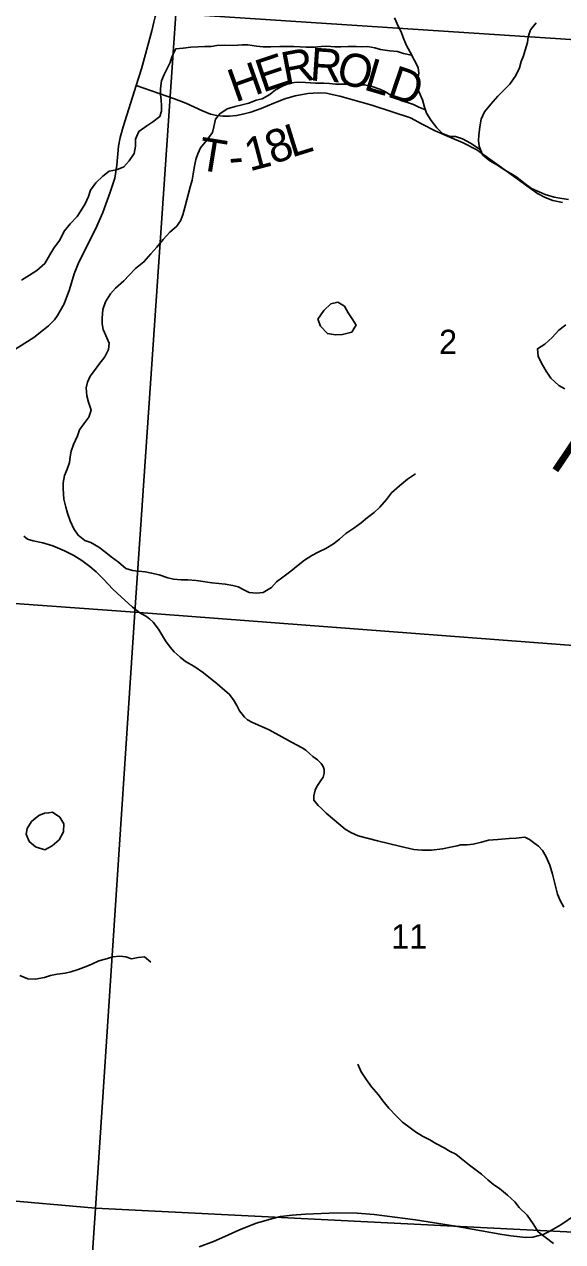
# Model space of a CAD drawing. Extents: x 0 to 34, y 0 to 22.
# Drawn here: x 24.527 to 25.453, y 16.992 to 19.088 of the extents above; entities that cross this region are included whole.
import ezdxf

# ---------------------------------------------------------------- set-up
doc = ezdxf.new("R2010")
doc.units = 0
for name, color, linetype in [('GM_X_Major_River', 7, 'Continuous'), ('GM_X_Major_River_Text', 7, 'Continuous'), ('GM_X_Minor_Lake', 7, 'Continuous'), ('GM_X_Minor_River', 7, 'Continuous'), ('GM_X_Section', 7, 'Continuous'), ('GM_X_Section_Text', 7, 'Continuous'), ('GM_X_State_Route', 7, 'Continuous'), ('GM_X_Township_Road', 7, 'Continuous'), ('GM_X_Township_Road_Text', 7, 'Continuous')]:
    doc.layers.add(name, color=color, linetype=linetype)

msp = doc.modelspace()

# ---------------------------------------------------------------- linework, layer by layer
at = {"layer": 'GM_X_Major_River'}
for points in [[(25.3133, 18.9253), (25.319, 18.9378), (25.3297, 18.9506), (25.342, 18.9645), (25.3515, 18.9747), (25.3626, 18.9856), (25.3726, 19.0004), (25.3791, 19.0136), (25.3822, 19.0242), (25.3861, 19.034), (25.3888, 19.0439), (25.3927, 19.0571), (25.3942, 19.067), (25.3981, 19.0787), (25.4077, 19.0908)], [(25.4633, 18.7865), (25.452, 18.7885), (25.4391, 18.7908), (25.4235, 18.7951), (25.4133, 18.8001), (25.3997, 18.8059), (25.3869, 18.8151), (25.3748, 18.8251), (25.3642, 18.8312), (25.3521, 18.8381), (25.3401, 18.8466), (25.328, 18.8535), (25.3155, 18.8638), (25.3095, 18.8783), (25.3089, 18.8882), (25.3093, 18.8976), (25.3109, 18.9117), (25.3133, 18.9253)], [(25.457, 18.4603), (25.4468, 18.466), (25.4332, 18.4787), (25.4249, 18.4909), (25.4171, 18.5046), (25.4111, 18.5168), (25.4104, 18.5297), (25.423, 18.5375), (25.4356, 18.5488), (25.4467, 18.5616), (25.4589, 18.5707)]]:
    msp.add_lwpolyline(points, dxfattribs=at)
at = {"layer": 'GM_X_Minor_Lake'}
for points in [[(25.0949, 18.5653), (25.0979, 18.57), (25.0914, 18.5813), (25.0842, 18.5916), (25.0781, 18.6029), (25.0667, 18.6101), (25.0546, 18.607), (25.0426, 18.5956), (25.032, 18.5808)], [(25.032, 18.5808), (25.037, 18.5683), (25.0487, 18.5558), (25.0628, 18.5536), (25.0745, 18.5544), (25.0904, 18.5582), (25.0949, 18.5653)], [(24.5694, 17.7304), (24.562, 17.7296), (24.5521, 17.7254), (24.5393, 17.7151), (24.5321, 17.703), (24.5303, 17.6935), (24.5352, 17.681), (24.5466, 17.6719), (24.5625, 17.6666)], [(24.5625, 17.6666), (24.575, 17.6731), (24.5871, 17.6838), (24.5946, 17.6974), (24.595, 17.7115), (24.5881, 17.7228), (24.5756, 17.7311), (24.5694, 17.7304)]]:
    msp.add_lwpolyline(points, dxfattribs=at)
at = {"layer": 'GM_X_Minor_River'}
for points in [[(25.313, 18.8698), (25.3078, 18.8753), (25.2949, 18.8836), (25.2812, 18.8912), (25.2691, 18.895), (25.2592, 18.8953), (25.2467, 18.9006), (25.2369, 18.9104), (25.227, 18.9225), (25.219, 18.9354), (25.2156, 18.9456), (25.2125, 18.9585), (25.206, 18.9725), (25.2033, 18.9854), (25.2044, 18.9949), (25.2059, 19.0044), (25.2047, 19.0138), (25.1983, 19.026), (25.191, 19.0404), (25.1842, 19.0532), (25.1788, 19.0657), (25.1754, 19.0752), (25.1704, 19.085), (25.1643, 19.0998)], [(25.1935, 19.0355), (25.1797, 19.038), (25.1694, 19.0414), (25.1558, 19.0429), (25.1399, 19.0452), (25.1304, 19.0478), (25.1179, 19.05), (25.1081, 19.0496), (25.0979, 19.0504), (25.0842, 19.0503), (25.0718, 19.0495), (25.0612, 19.0499), (25.0475, 19.0506), (25.0377, 19.0502), (25.0267, 19.049), (25.0123, 19.049), (25.0017, 19.0497), (24.9911, 19.0501), (24.9771, 19.0504), (24.9665, 19.05), (24.9514, 19.0496), (24.9381, 19.0496), (24.9264, 19.0507), (24.912, 19.0529), (24.9018, 19.0529), (24.887, 19.0521), (24.8723, 19.0525), (24.8586, 19.0517), (24.8484, 19.0501), (24.8378, 19.0501), (24.8265, 19.0497), (24.8136, 19.0489), (24.8003, 19.0474), (24.7879, 19.0462), (24.7807, 19.0325), (24.7781, 19.0227), (24.7736, 19.0132), (24.7676, 19.0018), (24.7634, 18.9908), (24.7616, 18.9779), (24.7616, 18.9677), (24.7624, 18.9578), (24.7632, 18.9483), (24.7632, 18.9388), (24.7602, 18.9294), (24.7481, 18.9202), (24.7379, 18.9138), (24.724, 18.9039), (24.7183, 18.8906), (24.7184, 18.8784), (24.7161, 18.8659), (24.7078, 18.853), (24.6984, 18.8431), (24.6856, 18.8378), (24.6731, 18.8355), (24.6621, 18.8271), (24.6504, 18.8153), (24.641, 18.8028), (24.6373, 18.7918), (24.632, 18.7793), (24.6245, 18.7671), (24.6181, 18.7573), (24.606, 18.7447), (24.5962, 18.7326), (24.5875, 18.7159), (24.5777, 18.7029), (24.571, 18.6916), (24.5623, 18.6767), (24.5487, 18.6646), (24.5362, 18.6566), (24.5223, 18.6478)], [(25.2172, 18.9409), (25.2061, 18.946), (25.1966, 18.9501), (25.1864, 18.9535), (25.1765, 18.9569), (25.1617, 18.9637), (25.1485, 18.9724), (25.1386, 18.9765), (25.1242, 18.9818), (25.1121, 18.9844), (25.1015, 18.9844), (25.0894, 18.9851), (25.0625, 18.9851), (25.0523, 18.9862), (25.0424, 18.9869), (25.028, 18.9873), (25.011, 18.9884), (24.9981, 18.9887), (24.9849, 18.9879), (24.9728, 18.9826), (24.9596, 18.9753), (24.9497, 18.9673), (24.9361, 18.9601), (24.9263, 18.9578), (24.9135, 18.9525), (24.9021, 18.9498), (24.89, 18.9471), (24.8764, 18.9429), (24.8635, 18.9345), (24.856, 18.925), (24.8534, 18.9118), (24.8512, 18.9019), (24.841, 18.8886), (24.83, 18.8757), (24.8259, 18.8654), (24.8225, 18.8556), (24.8192, 18.8412), (24.8177, 18.8305), (24.8158, 18.8199), (24.8128, 18.8101), (24.8099, 18.7968), (24.8069, 18.7862), (24.8035, 18.7729), (24.7998, 18.7604), (24.796, 18.7497), (24.7892, 18.7402), (24.7775, 18.7303), (24.7662, 18.7178), (24.7553, 18.7045), (24.7447, 18.6931), (24.733, 18.6791), (24.7187, 18.6676), (24.7073, 18.6562), (24.6983, 18.6467), (24.6843, 18.6338), (24.6757, 18.6243), (24.6666, 18.6106), (24.6625, 18.5974), (24.661, 18.5822), (24.6611, 18.5723), (24.6626, 18.5629), (24.6672, 18.5526), (24.6733, 18.5394), (24.6718, 18.5284), (24.6658, 18.5155), (24.6552, 18.5022), (24.6477, 18.4919), (24.6405, 18.4824), (24.636, 18.4722), (24.6338, 18.4623), (24.6346, 18.4487), (24.6373, 18.4377), (24.6419, 18.4237), (24.6381, 18.4115), (24.6294, 18.4001), (24.6223, 18.3902), (24.6185, 18.3796), (24.6118, 18.3648), (24.6076, 18.3534), (24.6058, 18.3436), (24.6047, 18.3337), (24.6009, 18.3219), (24.5964, 18.3113), (24.5938, 18.2988), (24.5942, 18.2882), (24.5954, 18.2707), (24.5985, 18.2567), (24.6015, 18.2465), (24.6061, 18.2332), (24.6126, 18.2192), (24.6195, 18.2082), (24.6312, 18.1995), (24.6415, 18.1958), (24.6551, 18.1879), (24.6673, 18.1788), (24.6767, 18.1712), (24.6893, 18.1618), (24.7018, 18.1512), (24.7135, 18.1478), (24.7238, 18.1467), (24.7351, 18.1452)], [(24.7351, 18.1452), (24.7461, 18.1433), (24.7594, 18.1399), (24.7741, 18.1351), (24.784, 18.1328), (24.7972, 18.1313), (24.8086, 18.1317), (24.823, 18.1302), (24.8347, 18.1284), (24.8499, 18.1265), (24.862, 18.1254), (24.873, 18.1243), (24.8859, 18.1217), (24.8953, 18.1194), (24.9048, 18.1145), (24.9143, 18.11), (24.9264, 18.1085), (24.9381, 18.1097), (24.9525, 18.1184), (24.9612, 18.1283), (24.9717, 18.1359), (24.9857, 18.1466), (24.9986, 18.1568), (25.0095, 18.1652), (25.0216, 18.1732), (25.0341, 18.1797), (25.0462, 18.1854), (25.0594, 18.1938), (25.0692, 18.2018), (25.0805, 18.2113), (25.0941, 18.2204), (25.107, 18.2299), (25.1175, 18.239), (25.1292, 18.2478), (25.139, 18.2569), (25.1504, 18.2702), (25.159, 18.2812), (25.1726, 18.2934), (25.1866, 18.3048), (25.2002, 18.3139)], [(24.5837, 17.4521), (24.5973, 17.454), (24.6071, 17.4563), (24.62, 17.4605), (24.6336, 17.4655), (24.6434, 17.4693), (24.6551, 17.475), (24.6661, 17.4784), (24.6794, 17.4819), (24.6915, 17.4834), (24.7017, 17.4819), (24.7115, 17.4785), (24.7233, 17.4808), (24.7342, 17.4824), (24.7449, 17.4729)], [(24.5193, 17.45), (24.533, 17.444), (24.5459, 17.4436), (24.5617, 17.4467), (24.572, 17.4501), (24.5837, 17.4521)], [(25.4377, 16.9885), (25.4236, 16.9991), (25.4111, 17.0082), (25.4027, 17.0222), (25.3925, 17.0369), (25.3784, 17.0502), (25.3712, 17.06), (25.3587, 17.0717), (25.345, 17.0831), (25.3351, 17.0895), (25.3249, 17.0982), (25.3139, 17.1076), (25.3025, 17.1163), (25.293, 17.1231), (25.279, 17.1349), (25.2695, 17.142), (25.26, 17.1466), (25.2494, 17.153), (25.2353, 17.1609), (25.2251, 17.167), (25.2122, 17.1734), (25.2005, 17.1809), (25.191, 17.1874), (25.1781, 17.1976), (25.1674, 17.2078), (25.1545, 17.2214), (25.1443, 17.2343), (25.1366, 17.2445), (25.1245, 17.2581), (25.1157, 17.2702), (25.107, 17.2838), (25.1009, 17.2975)]]:
    msp.add_lwpolyline(points, dxfattribs=at)
at = {"layer": 'GM_X_Section'}
for points in [[(25.8788, 20.042), (25.8109, 19.0399), (25.7909, 19.041), (24.8107, 19.1055), (24.8672, 20.1076)], [(23.7643, 19.174), (23.7939, 19.171), (24.788, 19.1066), (24.7175, 18.0761), (23.7006, 18.1492)], [(24.788, 19.1066), (24.8107, 19.1055), (25.7909, 19.041), (25.7287, 17.9991), (24.7175, 18.0761)], [(23.7006, 18.1492), (24.7175, 18.0761), (24.6497, 17.049), (23.6339, 17.1388)], [(25.7287, 17.9991), (25.6662, 16.9982), (24.6497, 17.049), (24.7175, 18.0761)], [(24.6497, 17.049), (24.5822, 16.0431), (23.5665, 16.1079), (23.6339, 17.1388)], [(24.6497, 17.049), (25.6662, 16.9982), (25.5991, 15.9654), (24.5822, 16.0431)]]:
    msp.add_lwpolyline(points, close=True, dxfattribs=at)
at = {"layer": 'GM_X_State_Route'}
for points in [[(24.7196, 18.9831), (24.7288, 19.0119), (24.7465, 19.0772), (24.75, 19.0924), (24.7525, 19.1011), (24.755, 19.1075), (24.7573, 19.1133), (24.7631, 19.1232), (24.7718, 19.1361), (24.796, 19.1672), (24.8254, 19.2044), (24.8724, 19.2592), (24.897, 19.2907), (24.9066, 19.3027), (24.9232, 19.3171), (24.9455, 19.33), (24.9742, 19.3445), (25.0104, 19.3714), (25.0913, 19.4315), (25.0986, 19.4369)], [(24.5064, 18.5256), (24.5436, 18.5492), (24.5602, 18.5622), (24.569, 18.5689), (24.5792, 18.5793), (24.5844, 18.5867), (24.5959, 18.6069), (24.6047, 18.6317), (24.6128, 18.6587), (24.6197, 18.676), (24.6393, 18.7153), (24.6497, 18.7355), (24.662, 18.7642), (24.6748, 18.7994), (24.6827, 18.8234), (24.6864, 18.8457), (24.6891, 18.8788), (24.6921, 18.8933), (24.6973, 18.9117), (24.7196, 18.9831)]]:
    msp.add_lwpolyline(points, dxfattribs=at)
at = {"layer": 'GM_X_Township_Road'}
for points in [[(24.7196, 18.9831), (24.7856, 18.9601), (24.8049, 18.9528), (24.8337, 18.9394), (24.8473, 18.9337), (24.8585, 18.9311), (24.8694, 18.93), (24.8804, 18.93), (24.8924, 18.9311), (24.9056, 18.9341), (24.9167, 18.9371), (24.9349, 18.9433), (24.9563, 18.9528), (24.9752, 18.9603), (24.9933, 18.9654), (25.0147, 18.9691), (25.0331, 18.9702), (25.0467, 18.9698), (25.07, 18.9645), (25.1252, 18.9491), (25.1617, 18.9373), (25.1914, 18.9272), (25.2117, 18.9162), (25.234, 18.9049), (25.2595, 18.8939), (25.2821, 18.8844), (25.3055, 18.872), (25.3442, 18.8444), (25.3959, 18.8071), (25.4102, 18.797), (25.4231, 18.7903), (25.4366, 18.7848), (25.4534, 18.7816)], [(24.5265, 18.2065), (24.5327, 18.2015), (24.5426, 18.1986), (24.559, 18.1953), (24.5761, 18.1899), (24.5965, 18.1813), (24.6123, 18.1733), (24.6263, 18.1646), (24.6398, 18.1546), (24.6509, 18.1453), (24.6635, 18.1326), (24.6794, 18.1153), (24.694, 18.1023), (24.713, 18.0842), (24.726, 18.0747), (24.7372, 18.0683), (24.7433, 18.0637), (24.7488, 18.0587), (24.7582, 18.0466), (24.7649, 18.035), (24.7703, 18.0262), (24.7779, 18.0156), (24.7852, 18.0075), (24.7954, 17.9982), (24.8045, 17.9907), (24.8187, 17.9829), (24.8355, 17.9712), (24.8587, 17.9523), (24.8724, 17.9412), (24.8797, 17.9348), (24.8871, 17.9251), (24.893, 17.9151), (24.8971, 17.9061), (24.9018, 17.9), (24.9061, 17.8952), (24.911, 17.8905), (24.92, 17.886), (24.9482, 17.8732), (24.9871, 17.8519), (25.0051, 17.8422), (25.0117, 17.8379), (25.0184, 17.832), (25.0238, 17.8272), (25.0316, 17.8215), (25.0378, 17.8154), (25.0416, 17.8102), (25.043, 17.8047), (25.0428, 17.7985), (25.0411, 17.7917), (25.0371, 17.7857), (25.0307, 17.7756), (25.0276, 17.7691), (25.0254, 17.7594), (25.0252, 17.7521), (25.0326, 17.7431), (25.0387, 17.7376), (25.0466, 17.7294), (25.0793, 17.7019), (25.089, 17.6962), (25.1015, 17.6908), (25.1347, 17.6818), (25.1752, 17.6721), (25.1975, 17.667), (25.2112, 17.6657), (25.2278, 17.6661), (25.2467, 17.668), (25.2633, 17.6715), (25.2719, 17.6735), (25.2783, 17.6749), (25.2889, 17.6749), (25.2995, 17.6765), (25.314, 17.6796), (25.3261, 17.6829), (25.3417, 17.6841), (25.3614, 17.6858), (25.3732, 17.6867), (25.3884, 17.6884), (25.3965, 17.6843), (25.4057, 17.6775), (25.4116, 17.6728), (25.4187, 17.6651), (25.4247, 17.6557), (25.4315, 17.6401), (25.4362, 17.6246), (25.4447, 17.5903), (25.4491, 17.5789), (25.4552, 17.5676)], [(24.8281, 16.9828), (24.8527, 16.9918), (24.8672, 16.9979), (24.8964, 17.0116), (24.9258, 17.0232), (24.9388, 17.0268), (24.9525, 17.0309), (24.968, 17.0346), (24.9879, 17.0371), (25.0107, 17.0389), (25.0656, 17.0412), (25.0998, 17.0405), (25.129, 17.0383), (25.1471, 17.0358), (25.2, 17.0291), (25.2654, 17.0187), (25.3457, 17.0047), (25.3641, 17.0016), (25.3899, 16.9986), (25.4022, 16.9993), (25.4109, 17.0013), (25.4199, 17.0039), (25.43, 17.0091), (25.4501, 17.0205), (25.4736, 17.0366)]]:
    msp.add_lwpolyline(points, dxfattribs=at)

# ---------------------------------------------------------------- texts
at = {"layer": 'GM_X_Major_River_Text'}
msp.add_text('Raccoon', height=0.0947, rotation=326.2028, dxfattribs=at).set_placement((25.4274, 18.3293))
at = {"layer": 'GM_X_Section_Text'}
for s, height, p in [('2', 0.0419, (25.2407, 18.5204)), ('11', 0.04186, (25.1582, 17.4964))]:
    msp.add_text(s, height=height, rotation=0, dxfattribs=at).set_placement(p)
at = {"layer": 'GM_X_Township_Road_Text'}
for s, rotation, p in [('R', 10.7772, (24.9755, 18.9833)), ('R', 356.1919, (25.0175, 18.9918)), ('O', 345.2861, (25.0612, 18.9892)), ('H', 19.5178, (24.8903, 18.9536)), ('E', 18.6531, (24.9372, 18.9703)), ('L', 343.5943, (25.1092, 18.9766)), ('D', 341.2033, (25.1493, 18.9648)), ('L', 17.283, (24.9871, 18.8587)), ('T', 350.8068, (24.8238, 18.8385)), ('1', 14.706, (24.9147, 18.8349)), ('8', 21.7303, (24.9557, 18.8461)), ('-', 4.704, (24.8808, 18.8311))]:
    msp.add_text(s, height=0.0568, rotation=rotation, dxfattribs=at).set_placement(p)

doc.saveas('drawing.dxf')
